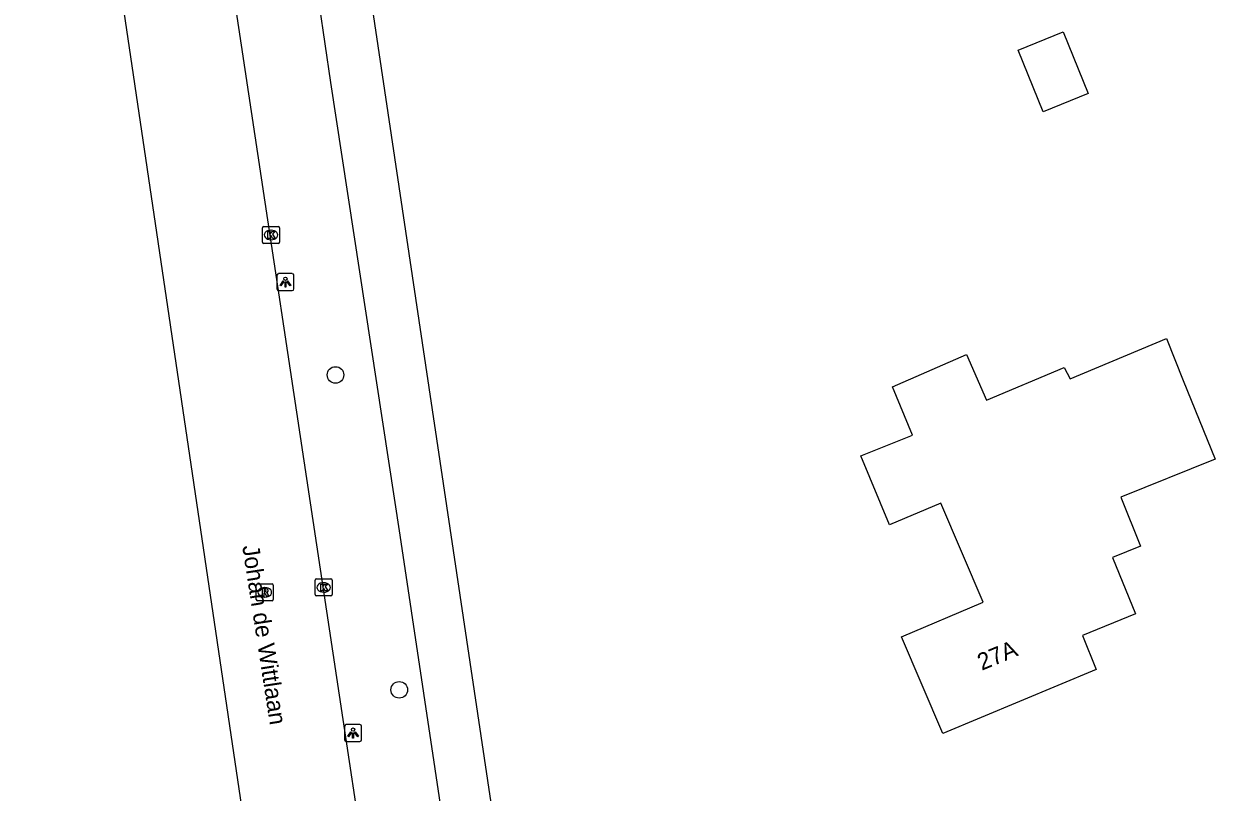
# Model space of a CAD drawing. Extents: x 162417 to 163721, y 384268 to 385416.
# Drawn here: x 163159.6 to 163229.8, y 384821.1 to 384866.4 of the extents above; entities that cross this region are included whole.
import ezdxf

# ---------------------------------------------------------------- set-up
doc = ezdxf.new("R2010")
doc.units = 0
for name, color, linetype in [('IMGEO_Boom', 7, 'Continuous'), ('IMGEO_Kolk', 7, 'Continuous'), ('IMGEO_Lichtpunt', 7, 'Continuous'), ('IMGEO_Openbare_ruimte_label', 7, 'Continuous'), ('IMGEO_Pand', 7, 'Continuous'), ('IMGEO_Pand_nummerreeks', 7, 'Continuous'), ('IMGEO_Rijbaan_lokaal_gesloten', 7, 'Continuous'), ('IMGEO_Rioolput', 7, 'Continuous'), ('IMGEO_Voetpad_open', 7, 'Continuous')]:
    doc.layers.add(name, color=color, linetype=linetype)

msp = doc.modelspace()

# ---------------------------------------------------------------- linework, layer by layer
at = {"layer": 'IMGEO_Boom'}
for centre in [(163177.939, 384845.707), (163181.699, 384827.146)]:
    msp.add_circle(centre, 0.489, dxfattribs=at)
at = {"layer": 'IMGEO_Kolk'}
for p, q in [((163173.636, 384853.535), (163173.636, 384854.387)), ((163173.711, 384854.461), (163174.563, 384854.461)), ((163174.637, 384854.387), (163174.637, 384853.535)), ((163174.147, 384853.681), (163174.122, 384853.681)), ((163174.124, 384854.241), (163174.149, 384854.241)), ((163174.563, 384853.461), (163173.711, 384853.461)), ((163176.744, 384832.756), (163176.744, 384833.608)), ((163176.819, 384833.682), (163177.671, 384833.682)), ((163177.232, 384833.462), (163177.257, 384833.462)), ((163177.745, 384833.608), (163177.745, 384832.756)), ((163177.671, 384832.682), (163176.819, 384832.682)), ((163177.255, 384832.902), (163177.23, 384832.902))]:
    msp.add_line(p, q, dxfattribs=at)
for points in [[(163173.636, 384853.535), (163173.636, 384854.387)], [(163173.711, 384854.461), (163174.563, 384854.461)], [(163174.637, 384854.387), (163174.637, 384853.535)], [(163173.957, 384854.161), (163174.08, 384854.161), (163174.08, 384854.01), (163174.21, 384854.161), (163174.374, 384854.161), (163174.228, 384854.01), (163174.381, 384853.761), (163174.229, 384853.761), (163174.144, 384853.925), (163174.08, 384853.858), (163174.08, 384853.761), (163173.957, 384853.761), (163173.957, 384854.161)], [(163174.563, 384853.461), (163173.711, 384853.461)], [(163176.744, 384832.756), (163176.744, 384833.608)], [(163176.819, 384833.682), (163177.671, 384833.682)], [(163177.065, 384833.382), (163177.188, 384833.382), (163177.188, 384833.231), (163177.318, 384833.382), (163177.482, 384833.382), (163177.336, 384833.231), (163177.489, 384832.982), (163177.337, 384832.982), (163177.252, 384833.146), (163177.188, 384833.079), (163177.188, 384832.982), (163177.065, 384832.982), (163177.065, 384833.382)], [(163177.745, 384833.608), (163177.745, 384832.756)], [(163177.671, 384832.682), (163176.819, 384832.682)]]:
    msp.add_lwpolyline(points, dxfattribs=at)
for centre, start, end in [((163173.713, 384854.385), 91.55205, 178.44795), ((163173.713, 384854.385), 91.55205, 178.44795), ((163174.561, 384854.385), 1.55205, 88.44795), ((163174.561, 384854.385), 1.55205, 88.44795), ((163173.713, 384853.537), 181.55205, 268.44795), ((163173.713, 384853.537), 181.55205, 268.44795), ((163174.561, 384853.537), 271.55205, 358.44795), ((163174.561, 384853.537), 271.55205, 358.44795), ((163176.821, 384833.606), 91.55205, 178.44795), ((163176.821, 384833.606), 91.55205, 178.44795), ((163177.669, 384833.606), 1.55205, 88.44795), ((163177.669, 384833.606), 1.55205, 88.44795), ((163176.821, 384832.758), 181.55205, 268.44795), ((163176.821, 384832.758), 181.55205, 268.44795), ((163177.669, 384832.758), 271.55205, 358.44795), ((163177.669, 384832.758), 271.55205, 358.44795)]:
    msp.add_arc(centre, 0.0765, start, end, dxfattribs=at)
for centre, major_axis, ratio, start_param, end_param in [((163174.123, 384853.961), (-0.387, 0.002), 0.722429, 4.712389, 7.853982), ((163174.148, 384853.961), (-0.39, 0.002), 0.717154, 1.570796, 4.712389), ((163177.231, 384833.182), (-0.387, 0.002), 0.722429, 4.712389, 7.853982), ((163177.256, 384833.182), (-0.39, 0.002), 0.717154, 1.570796, 4.712389)]:
    msp.add_ellipse(centre, major_axis=major_axis, ratio=ratio, start_param=start_param, end_param=end_param, dxfattribs=at)
at = {"layer": 'IMGEO_Lichtpunt'}
for p, q in [((163174.488, 384851.584), (163174.488, 384850.777)), ((163174.488, 384851.584), (163174.488, 384850.777)), ((163175.39, 384851.679), (163174.582, 384851.679)), ((163175.39, 384851.679), (163174.582, 384851.679)), ((163175.484, 384850.777), (163175.484, 384851.584)), ((163175.484, 384850.777), (163175.484, 384851.584)), ((163174.582, 384850.683), (163175.39, 384850.683)), ((163174.582, 384850.683), (163175.39, 384850.683)), ((163178.475, 384825.003), (163178.475, 384824.196)), ((163178.475, 384825.003), (163178.475, 384824.196)), ((163179.377, 384825.098), (163178.569, 384825.098)), ((163179.377, 384825.098), (163178.569, 384825.098)), ((163179.471, 384824.196), (163179.471, 384825.003)), ((163179.471, 384824.196), (163179.471, 384825.003)), ((163178.569, 384824.102), (163179.377, 384824.102)), ((163178.569, 384824.102), (163179.377, 384824.102))]:
    msp.add_line(p, q, dxfattribs=at)
for points in [[(163174.862, 384851.248), (163174.901, 384851.22), (163174.713, 384850.958), (163174.675, 384850.985), (163174.862, 384851.248)], [(163174.964, 384851.2), (163175.011, 384851.2), (163175.011, 384850.878), (163174.964, 384850.878), (163174.964, 384851.2)], [(163175.074, 384851.22), (163175.112, 384851.247), (163175.299, 384850.985), (163175.26, 384850.957), (163175.074, 384851.22)], [(163178.849, 384824.667), (163178.888, 384824.639), (163178.7, 384824.377), (163178.662, 384824.404), (163178.849, 384824.667)], [(163178.951, 384824.619), (163178.998, 384824.619), (163178.998, 384824.297), (163178.951, 384824.297), (163178.951, 384824.619)], [(163179.061, 384824.639), (163179.099, 384824.666), (163179.286, 384824.404), (163179.247, 384824.376), (163179.061, 384824.639)]]:
    msp.add_lwpolyline(points, dxfattribs=at)
for centre in [(163174.987, 384851.382), (163178.974, 384824.801)]:
    msp.add_circle(centre, 0.0994, dxfattribs=at)
for centre, start, end in [((163174.582, 384851.584), 90, 180), ((163174.582, 384851.584), 90, 180), ((163175.39, 384851.584), 0, 90), ((163175.39, 384851.584), 0, 90), ((163174.582, 384850.777), 180, 270), ((163174.582, 384850.777), 180, 270), ((163175.39, 384850.777), 270, 0), ((163175.39, 384850.777), 270, 360), ((163178.569, 384825.003), 90, 180), ((163178.569, 384825.003), 90, 180), ((163179.377, 384825.003), 0, 90), ((163179.377, 384825.003), 0, 90), ((163178.569, 384824.196), 180, 270), ((163178.569, 384824.196), 180, 270), ((163179.377, 384824.196), 270, 0), ((163179.377, 384824.196), 270, 360)]:
    msp.add_arc(centre, 0.0946, start, end, dxfattribs=at)
at = {"layer": 'IMGEO_Pand'}
for points in [[(163218.184, 384864.853), (163220.841, 384865.931), (163222.313, 384862.302), (163219.657, 384861.224), (163218.184, 384864.853)], [(163227.923, 384845.387), (163229.802, 384840.753), (163224.242, 384838.497), (163225.407, 384835.624), (163223.757, 384834.954), (163225.11, 384831.618), (163221.98, 384830.348), (163222.787, 384828.346), (163213.737, 384824.576), (163211.31, 384830.26), (163216.121, 384832.314), (163213.618, 384838.15), (163210.603, 384836.863), (163208.906, 384840.934), (163211.965, 384842.153), (163210.776, 384844.998), (163215.14, 384846.909), (163216.318, 384844.229), (163220.899, 384846.157), (163221.245, 384845.478), (163226.923, 384847.852), (163227.923, 384845.387)]]:
    msp.add_lwpolyline(points, dxfattribs=at)
at = {"layer": 'IMGEO_Rijbaan_lokaal_gesloten'}
for points in [[(163172.668, 384818.516), (163159.564, 384907.094), (163168.293, 384913.998)], [(163168.375, 384891.762), (163181.052, 384807.665)]]:
    msp.add_lwpolyline(points, dxfattribs=at)
at = {"layer": 'IMGEO_Rioolput'}
for p, q in [((163173.269, 384832.468), (163173.269, 384833.32)), ((163173.344, 384833.394), (163174.196, 384833.394)), ((163174.27, 384833.32), (163174.27, 384832.468)), ((163173.78, 384832.614), (163173.755, 384832.614)), ((163173.757, 384833.174), (163173.782, 384833.174)), ((163174.196, 384832.394), (163173.344, 384832.394))]:
    msp.add_line(p, q, dxfattribs=at)
for points in [[(163173.269, 384832.468), (163173.269, 384833.32)], [(163173.344, 384833.394), (163174.196, 384833.394)], [(163174.27, 384833.32), (163174.27, 384832.468)], [(163173.858, 384833.092), (163173.606, 384833.094), (163173.606, 384832.694)], [(163173.606, 384832.694), (163173.73, 384832.694), (163173.73, 384832.856), (163173.741, 384832.856)], [(163173.784, 384833.013), (163173.73, 384833.013), (163173.73, 384832.932)], [(163173.73, 384832.932), (163173.782, 384832.932)], [(163173.788, 384832.827), (163173.859, 384832.694), (163173.999, 384832.694), (163173.934, 384832.82)], [(163174.196, 384832.394), (163173.344, 384832.394)]]:
    msp.add_lwpolyline(points, dxfattribs=at)
for centre, radius, start, end in [((163173.346, 384833.318), 0.0765, 91.55205, 178.44795), ((163173.346, 384833.318), 0.0765, 91.55205, 178.44795), ((163174.194, 384833.318), 0.0765, 1.55205, 88.44795), ((163174.194, 384833.318), 0.0765, 1.55205, 88.44795), ((163173.74, 384832.803), 0.0533, 26.02933, 88.69889), ((163173.766, 384833.121), 0.19, 274.7715, 282.96867), ((163173.79, 384832.917), 0.0964, 77.00612, 93.18647), ((163173.804, 384832.974), 0.0378, 276.66336, 79.67722), ((163173.857, 384832.982), 0.109, 350.36119, 89.41601), ((163173.855, 384832.982), 0.112, 277.58423, 350.98172), ((163173.839, 384832.767), 0.108, 29.51342, 73.79051), ((163173.346, 384832.47), 0.0765, 181.55205, 268.44795), ((163173.346, 384832.47), 0.0765, 181.55205, 268.44795), ((163174.194, 384832.47), 0.0765, 271.55205, 358.44795), ((163174.194, 384832.47), 0.0765, 271.55205, 358.44795)]:
    msp.add_arc(centre, radius, start, end, dxfattribs=at)
for centre, major_axis, ratio, start_param, end_param in [((163173.756, 384832.894), (-0.387, 0.002), 0.722429, 4.712389, 7.853982), ((163173.781, 384832.894), (-0.39, 0.002), 0.717154, 1.570796, 4.712389)]:
    msp.add_ellipse(centre, major_axis=major_axis, ratio=ratio, start_param=start_param, end_param=end_param, dxfattribs=at)
at = {"layer": 'IMGEO_Voetpad_open'}
for points in [[(163175.984, 384894.871), (163189.317, 384805.604)], [(163173.131, 384893.686), (163174.611, 384883.435), (163175.599, 384877.142), (163176.027, 384874.074), (163176.986, 384867.512), (163177.654, 384862.939), (163181.731, 384836.256), (163185.853, 384808.72), (163186.458, 384804.456)]]:
    msp.add_lwpolyline(points, dxfattribs=at)

# ---------------------------------------------------------------- texts
at = {"layer": 'IMGEO_Openbare_ruimte_label'}
msp.add_text('Johan de Wittlaan', height=1, rotation=278.8028, dxfattribs=at).set_placement((163172.441, 384835.607))
at = {"layer": 'IMGEO_Pand_nummerreeks'}
msp.add_text('27A', height=1, rotation=22.61537, dxfattribs=at).set_placement((163216.042, 384828.266))

doc.saveas('drawing.dxf')
